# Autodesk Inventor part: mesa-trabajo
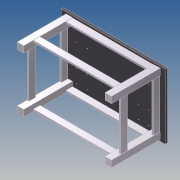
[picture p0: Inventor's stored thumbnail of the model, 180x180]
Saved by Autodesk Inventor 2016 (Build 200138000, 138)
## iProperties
Created: 2012-05
Part Number: mesa-trabajo
Material: Generic
Document SubType Name: Modeling
Designer: julian.chica
Density: 1 g/cm^3
Appearance: Default
Author: julian.chica
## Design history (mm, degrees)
sketch "Sketch2"
  geometry: L1 (-800, 500)-(800, 500); L2 (800, 500)-(800, -500); L3 (800, -500)-(-800, -500); L4 (-800, -500)-(-800, 500); 3 further points
  constraints: 8 end point, 2 midpoint, 2 parallel, 1 horizontal, 1 horizontal alignment, 1 perpendicular, 1 vertical alignment
  dimensions: "d0" = 1600 distance of L2.end L3.end; "d1" = 1000 distance of L1.end L2.end
extrude "Extrusion1" new body sketch "Sketch2" distance "d2" = 38.1; taper "d3" = 0 deg
sketch "Sketch3"
  geometry: L1 (800, 500)-(800, -500) reference; L2 (-800, 500)-(800, 500) reference; L3 (-800, -500)-(-800, 500) reference; L4 (800, -500)-(-800, -500) reference; L5 (720, 470)-(720, -470); L6 (720, -470)-(-720, -470); L7 (-720, -470)-(-720, 470); L8 (-720, 470)-(720, 470); L9 (694.6, 444.6)-(694.6, -444.6); L10 (694.6, -444.6)-(-694.6, -444.6); L11 (-694.6, -444.6)-(-694.6, 444.6); L12 (-694.6, 444.6)-(694.6, 444.6); 1 further point
  constraints: 16 end point, 3 other
  dimensions: "d4" = 25.4 distance between parallel lines of L12 L8; "d8" = 30 distance between parallel lines of L2 L8; "d9" = 30 distance between parallel lines of L4 L6; "d10" = 80 distance between parallel lines of L1 L5; "d11" = 80 distance between parallel lines of L3 L7
extrude "Extrusion2" join sketch "Sketch3" distance "d6" = 100; taper "d7" = 0 deg
sketch "Sketch4"
  geometry: L1 (-720, 470)-(-630, 470); L2 (-630, 470)-(-630, 380); L3 (-630, 380)-(-720, 380); L4 (-720, 380)-(-720, 470); L5 (-725, 375)-(-625, 375); L6 (-625, 375)-(-625, 475); L7 (-625, 475)-(-725, 475); L8 (-725, 475)-(-725, 375); L9 (625, 375)-(725, 375); L10 (725, 375)-(725, 475); L11 (725, 475)-(625, 475); L12 (625, 475)-(625, 375); L13 (-725, -475)-(-625, -475); L14 (-625, -475)-(-625, -375); L15 (-625, -375)-(-725, -375); L16 (-725, -375)-(-725, -475); L17 (625, -475)-(725, -475); L18 (725, -475)-(725, -375); L19 (725, -375)-(625, -375); L20 (625, -375)-(625, -475); 3 further points
  constraints: 40 end point, 4 parallel, 2 horizontal, 2 perpendicular, 1 vertical, 27 other
  dimensions: "d12" = 90 distance of L2.end L3.end; "d13" = 90 distance of L1.end L2.end; "d14" = 5 distance between parallel lines of L3 L5; "d17" = 1350 distance of L5.start L9.start; "d20" = 850 distance of L5.start L13.start
extrude "Extrusion3" join sketch "Sketch4" distance "d23" = 750; taper "d24" = 0 deg
pattern_linear "Rectangular Pattern1" dims "d27" = 500
sketch "Sketch5"
  geometry: L1 (800, -500)-(-800, -500) reference; L2 (800, 500)-(800, -500) reference; 5 further points
  constraints: 2 horizontal alignment, 2 vertical alignment
  dimensions: "d28" = 160 distance of point (550, -380) point (390, -380); "d29" = 205 distance of point (390, -380) point (390, -175); "d30" = 120 distance from line of L1 point (550, -380); "d31" = 250 distance from line of L2 point (550, -380)
hole "Hole1" sketch "Sketch5" at (390, -175), (550, -175), (550, -380), (390, -380) diameter "d32" = 9; stored, may be unused: countersink angle "d36" = 90 deg, drill point angle "d38" = 118 deg; dims "d33" = 6, "d34" = 4, "d35" = 2, "d37" = 8
pattern_linear "Rectangular Pattern2" dims "d41" = 950
body "Solid1"
